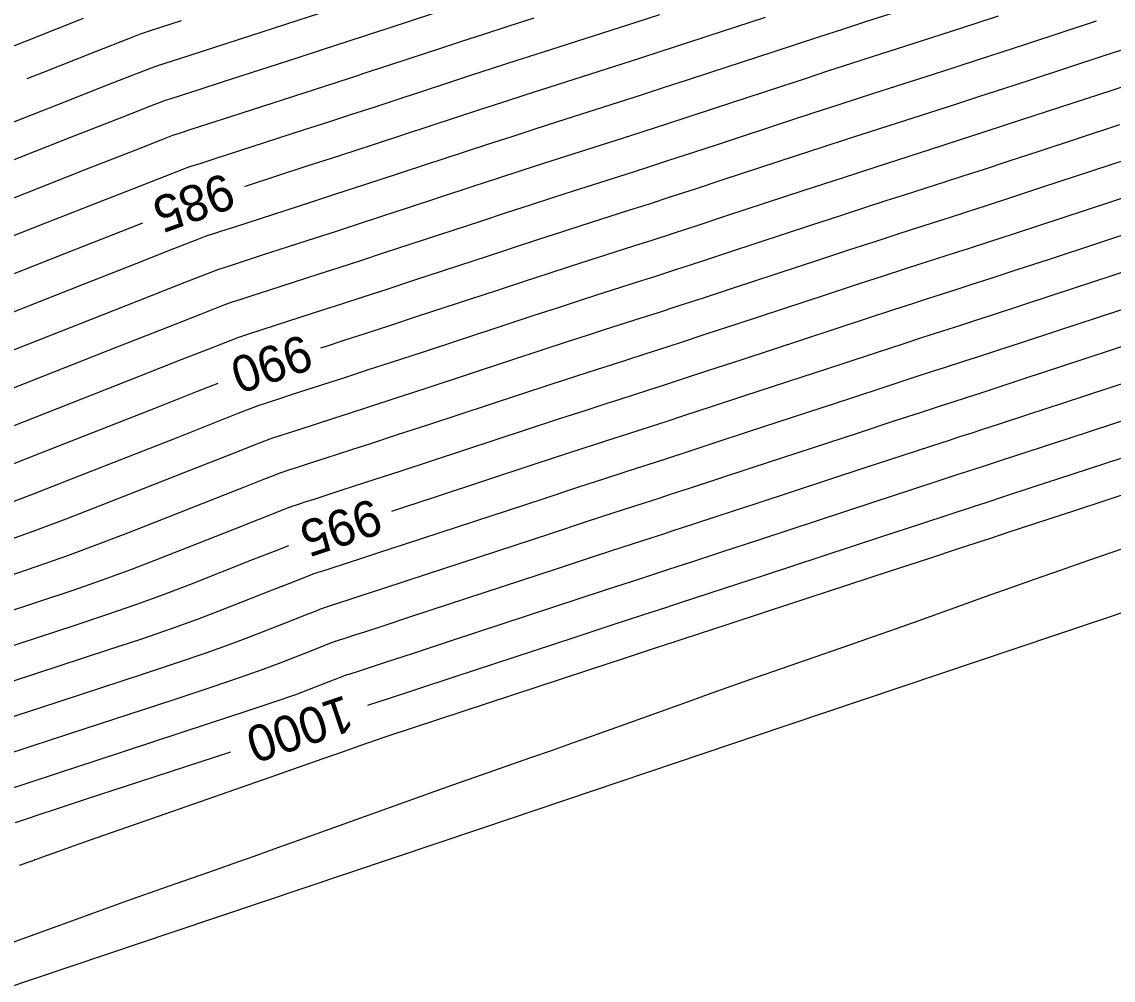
# Model space of a CAD drawing. Extents: x 2175772 to 2185556, y 721391 to 722853.
# Drawn here: x 2178849.6 to 2178934, y 721822.4 to 721896.5 of the extents above; entities that cross this region are included whole.
import ezdxf

# ---------------------------------------------------------------- set-up
doc = ezdxf.new("R2010")
doc.units = 0
for name, color, linetype in [('DT_X_Contour_Major', 7, 'Continuous'), ('DT_X_Contour_Minor', 7, 'Continuous'), ('DT_X_TIN_Hull', 7, 'Continuous')]:
    doc.layers.add(name, color=color, linetype=linetype)

msp = doc.modelspace()

# ---------------------------------------------------------------- linework, layer by layer
at = {"layer": 'DT_X_Contour_Major'}
for points in [[(2178850.015, 721892.08), (2178851.287, 721892.58), (2178855.384, 721894.192), (2178857.887, 721895.174), (2178858.796, 721895.527), (2178859.095, 721895.63), (2178859.488, 721895.759), (2178860.443, 721896.069), (2178861.959, 721896.56)], [(2178907.086, 721896.807), (2178902.576, 721895.326), (2178900.862, 721894.765), (2178899.102, 721894.193), (2178897.295, 721893.609), (2178895.442, 721893.013), (2178890.44, 721891.409), (2178888.585, 721890.813), (2178886.774, 721890.227), (2178885.006, 721889.652), (2178883.281, 721889.088), (2178877.024, 721887.035), (2178875.286, 721886.467), (2178873.524, 721885.895), (2178871.739, 721885.317), (2178866.948, 721883.769), (2178866.835, 721883.733)], [(2178935.904, 721891.824), (2178933.887, 721891.162), (2178927.874, 721889.189), (2178925.737, 721888.489), (2178923.836, 721887.869), (2178922.171, 721887.328), (2178920.742, 721886.868), (2178917.247, 721885.747), (2178915.816, 721885.286), (2178914.145, 721884.744), (2178912.235, 721884.121), (2178910.085, 721883.416), (2178904.033, 721881.43), (2178901.885, 721880.726), (2178899.98, 721880.104), (2178898.319, 721879.565), (2178896.901, 721879.108), (2178893.445, 721878), (2178892.026, 721877.543), (2178890.359, 721877.002), (2178888.445, 721876.377), (2178886.284, 721875.669), (2178880.191, 721873.669), (2178878.038, 721872.962), (2178876.147, 721872.344), (2178874.518, 721871.813), (2178873.152, 721871.37), (2178872.713, 721871.229)], [(2178858.933, 721880.894), (2178857.236, 721880.226), (2178852.9, 721878.519), (2178839.721, 721873.33)], [(2178936.883, 721877.801), (2178929.334, 721875.323), (2178926.765, 721874.48), (2178924.721, 721873.811), (2178923.201, 721873.316), (2178922.205, 721872.994), (2178920.249, 721872.367), (2178919.251, 721872.044), (2178917.724, 721871.547), (2178915.669, 721870.874), (2178913.085, 721870.026), (2178905.489, 721867.533), (2178902.907, 721866.686), (2178900.858, 721866.015), (2178899.343, 721865.521), (2178898.36, 721865.203), (2178896.451, 721864.591), (2178895.466, 721864.273), (2178893.944, 721863.777), (2178891.884, 721863.102), (2178889.287, 721862.25), (2178881.643, 721859.741), (2178879.051, 721858.89), (2178878.197, 721858.61)], [(2178864.773, 721868.496), (2178863.184, 721867.871), (2178860.205, 721866.699), (2178851.147, 721863.132), (2178847.944, 721861.886)], [(2178939.879, 721864.439), (2178930.794, 721861.457), (2178927.794, 721860.472), (2178925.606, 721859.754), (2178924.231, 721859.304), (2178923.668, 721859.12), (2178923.251, 721858.986), (2178921.303, 721858.349), (2178919.103, 721857.627), (2178916.084, 721856.636), (2178906.945, 721853.636), (2178903.929, 721852.646), (2178900.366, 721851.477), (2178899.819, 721851.299), (2178899.457, 721851.183), (2178898.907, 721851.003), (2178897.529, 721850.551), (2178895.323, 721849.827), (2178892.29, 721848.831), (2178883.096, 721845.813), (2178880.065, 721844.818), (2178877.869, 721844.097), (2178876.506, 721843.65), (2178876.344, 721843.597)], [(2178870.231, 721855.949), (2178869.133, 721855.517), (2178867.51, 721854.878), (2178862.573, 721852.934), (2178860.627, 721852.19), (2178858.49, 721851.413), (2178856.163, 721850.605), (2178853.645, 721849.766), (2178846.677, 721847.485)], [(2178865.742, 721839.993), (2178857.606, 721837.33), (2178854.6, 721836.346), (2178852.347, 721835.606), (2178850.846, 721835.11), (2178850.098, 721834.86), (2178849.105, 721834.517)]]:
    msp.add_lwpolyline(points, dxfattribs=at)
at = {"layer": 'DT_X_Contour_Minor'}
for points in [[(2178919.572, 721897.967), (2178914.845, 721896.452), (2178913.068, 721895.88), (2178911.282, 721895.302), (2178909.488, 721894.719), (2178907.686, 721894.129), (2178902.868, 721892.547), (2178901.067, 721891.957), (2178899.277, 721891.375), (2178897.5, 721890.8), (2178895.734, 721890.232), (2178891.041, 721888.727), (2178889.273, 721888.159), (2178887.491, 721887.582), (2178885.694, 721886.997), (2178883.882, 721886.404), (2178879.029, 721884.811), (2178877.227, 721884.22), (2178875.458, 721883.643), (2178873.723, 721883.079), (2178872.022, 721882.528), (2178866.046, 721880.597), (2178864.964, 721880.246), (2178864.282, 721880.025), (2178864.001, 721879.933), (2178863.788, 721879.859), (2178863.139, 721879.607), (2178861.351, 721878.906), (2178858.425, 721877.755), (2178854.361, 721876.155), (2178842.006, 721871.29)], [(2178835.15, 721877.409), (2178849.978, 721883.248), (2178854.856, 721885.168), (2178858.367, 721886.549), (2178860.513, 721887.39), (2178861.292, 721887.693), (2178861.548, 721887.782), (2178861.885, 721887.892), (2178862.703, 721888.158), (2178864.003, 721888.578), (2178865.783, 721889.154), (2178873.126, 721891.528), (2178874.941, 721892.117), (2178876.619, 721892.663), (2178878.158, 721893.168), (2178882.08, 721894.455), (2178883.63, 721894.962), (2178885.34, 721895.518), (2178887.209, 721896.121), (2178889.237, 721896.773)], [(2178898.926, 721897.011), (2178897.09, 721896.418), (2178895.151, 721895.794), (2178889.839, 721894.091), (2178887.897, 721893.467), (2178886.057, 721892.872), (2178884.318, 721892.307), (2178882.68, 721891.772), (2178878.449, 721890.382), (2178876.821, 721889.849), (2178875.113, 721889.292), (2178873.325, 721888.711), (2178871.456, 721888.106), (2178866.366, 721886.462), (2178864.684, 721885.918), (2178863.457, 721885.521), (2178862.684, 721885.27), (2178862.366, 721885.165), (2178862.124, 721885.082), (2178861.388, 721884.796), (2178859.362, 721884.001), (2178856.046, 721882.697), (2178851.439, 721880.884), (2178837.435, 721875.369)], [(2178844.135, 721892.704), (2178850.097, 721895.051), (2178854.389, 721896.739)], [(2178925.12, 721896.894), (2178923.305, 721896.303), (2178921.553, 721895.736), (2178919.865, 721895.192), (2178915.445, 721893.776), (2178913.755, 721893.232), (2178911.998, 721892.663), (2178910.175, 721892.069), (2178908.286, 721891.451), (2178903.159, 721889.768), (2178901.271, 721889.15), (2178899.453, 721888.557), (2178897.705, 721887.991), (2178896.026, 721887.451), (2178891.642, 721886.046), (2178889.961, 721885.505), (2178888.208, 721884.937), (2178886.382, 721884.342), (2178884.482, 721883.72), (2178879.32, 721882.025), (2178877.429, 721881.406), (2178875.63, 721880.818), (2178873.922, 721880.262), (2178872.304, 721879.738), (2178868.112, 721878.384), (2178866.728, 721877.936), (2178865.717, 721877.609), (2178865.081, 721877.403), (2178864.819, 721877.317), (2178864.62, 721877.248), (2178864.014, 721877.013), (2178862.346, 721876.358), (2178859.615, 721875.284), (2178855.822, 721873.791), (2178844.291, 721869.251)], [(2178847.057, 721887.976), (2178852.477, 721890.109), (2178856.378, 721891.644), (2178858.762, 721892.579), (2178859.628, 721892.916), (2178859.913, 721893.014), (2178860.287, 721893.137), (2178861.196, 721893.432), (2178862.64, 721893.899), (2178864.619, 721894.539), (2178872.729, 721897.16)], [(2178848.518, 721885.612), (2178853.666, 721887.639), (2178857.373, 721889.096), (2178859.638, 721889.985), (2178860.46, 721890.304), (2178860.731, 721890.398), (2178861.086, 721890.515), (2178861.95, 721890.795), (2178863.321, 721891.239), (2178865.201, 721891.847), (2178870.891, 721893.685), (2178872.928, 721894.344), (2178874.769, 721894.941), (2178876.416, 721895.478), (2178877.868, 721895.953), (2178881.479, 721897.139)], [(2178932.688, 721896.507), (2178927.29, 721894.735), (2178925.326, 721894.092), (2178923.482, 721893.491), (2178921.759, 721892.933), (2178920.157, 721892.418), (2178916.046, 721891.099), (2178914.442, 721890.583), (2178912.714, 721890.023), (2178910.862, 721889.42), (2178908.885, 721888.773), (2178903.45, 721886.988), (2178901.476, 721886.342), (2178899.629, 721885.74), (2178897.909, 721885.183), (2178896.318, 721884.67), (2178892.243, 721883.364), (2178890.65, 721882.851), (2178888.925, 721882.292), (2178887.069, 721881.687), (2178885.083, 721881.037), (2178879.61, 721879.24), (2178877.632, 721878.591), (2178875.802, 721877.993), (2178874.12, 721877.446), (2178872.587, 721876.949), (2178868.695, 721875.692), (2178867.409, 721875.276), (2178866.471, 721874.972), (2178865.88, 721874.78), (2178865.637, 721874.701), (2178865.452, 721874.637), (2178864.889, 721874.418), (2178863.34, 721873.81), (2178860.805, 721872.813), (2178857.283, 721871.427), (2178846.576, 721867.211)], [(2178935.208, 721894.465), (2178933.287, 721893.835), (2178927.582, 721891.962), (2178925.531, 721891.29), (2178923.659, 721890.68), (2178921.965, 721890.131), (2178920.45, 721889.643), (2178916.646, 721888.423), (2178915.129, 721887.935), (2178913.43, 721887.384), (2178911.548, 721886.77), (2178909.485, 721886.095), (2178903.741, 721884.209), (2178901.68, 721883.534), (2178899.804, 721882.922), (2178898.114, 721882.374), (2178896.609, 721881.889), (2178892.844, 721880.682), (2178891.338, 721880.197), (2178889.642, 721879.647), (2178887.757, 721879.032), (2178885.683, 721878.353), (2178879.901, 721876.454), (2178877.835, 721875.777), (2178875.974, 721875.169), (2178874.319, 721874.63), (2178872.869, 721874.16), (2178869.277, 721872.999), (2178868.09, 721872.615), (2178867.224, 721872.335), (2178866.679, 721872.158), (2178866.455, 721872.084), (2178866.284, 721872.025), (2178865.765, 721871.824), (2178864.335, 721871.263), (2178861.995, 721870.342), (2178858.744, 721869.063), (2178848.862, 721865.172)], [(2178934.486, 721888.49), (2178928.166, 721886.416), (2178925.943, 721885.687), (2178924.013, 721885.057), (2178922.377, 721884.526), (2178921.035, 721884.093), (2178917.847, 721883.071), (2178916.503, 721882.638), (2178914.861, 721882.105), (2178912.922, 721881.472), (2178910.685, 721880.738), (2178904.324, 721878.65), (2178902.089, 721877.918), (2178900.156, 721877.286), (2178898.524, 721876.756), (2178897.193, 721876.327), (2178894.047, 721875.319), (2178892.714, 721874.889), (2178891.076, 721874.357), (2178889.133, 721873.722), (2178886.885, 721872.985), (2178880.482, 721870.883), (2178878.24, 721870.148), (2178876.319, 721869.519), (2178874.717, 721868.997), (2178873.435, 721868.581), (2178870.442, 721867.614), (2178869.453, 721867.294), (2178868.731, 721867.061), (2178868.277, 721866.913), (2178868.09, 721866.852), (2178867.948, 721866.803), (2178867.515, 721866.635), (2178866.324, 721866.167), (2178864.374, 721865.401), (2178861.666, 721864.334), (2178853.432, 721861.092), (2178850.481, 721859.947), (2178847.802, 721858.942)], [(2178935.085, 721885.818), (2178928.458, 721883.642), (2178926.148, 721882.885), (2178924.19, 721882.246), (2178922.583, 721881.723), (2178921.327, 721881.318), (2178918.447, 721880.395), (2178917.19, 721879.989), (2178915.577, 721879.465), (2178913.609, 721878.822), (2178911.285, 721878.06), (2178904.615, 721875.871), (2178902.294, 721875.11), (2178900.331, 721874.469), (2178898.728, 721873.947), (2178897.485, 721873.546), (2178894.648, 721872.637), (2178893.402, 721872.235), (2178891.793, 721871.712), (2178889.821, 721871.067), (2178887.485, 721870.302), (2178880.772, 721868.097), (2178878.443, 721867.333), (2178876.491, 721866.695), (2178874.916, 721866.181), (2178873.717, 721865.792), (2178871.024, 721864.922), (2178870.134, 721864.634), (2178869.485, 721864.424), (2178869.076, 721864.291), (2178868.908, 721864.236), (2178868.78, 721864.192), (2178868.39, 721864.04), (2178867.318, 721863.62), (2178865.564, 721862.93), (2178863.127, 721861.97), (2178855.718, 721859.053), (2178853.017, 721858.008), (2178850.474, 721857.06), (2178848.087, 721856.209)], [(2178935.684, 721883.145), (2178926.354, 721880.084), (2178924.367, 721879.434), (2178922.789, 721878.921), (2178921.62, 721878.544), (2178919.048, 721877.719), (2178917.877, 721877.341), (2178916.293, 721876.826), (2178914.295, 721876.173), (2178911.885, 721875.382), (2178904.906, 721873.091), (2178902.498, 721872.302), (2178900.507, 721871.651), (2178898.933, 721871.139), (2178897.777, 721870.765), (2178895.249, 721869.955), (2178894.09, 721869.581), (2178892.51, 721869.067), (2178890.509, 721868.412), (2178888.086, 721867.618), (2178881.063, 721865.312), (2178878.646, 721864.519), (2178876.663, 721863.87), (2178875.115, 721863.364), (2178874, 721863.002), (2178871.606, 721862.229), (2178870.815, 721861.973), (2178870.238, 721861.787), (2178869.875, 721861.669), (2178869.725, 721861.62), (2178869.612, 721861.58), (2178869.266, 721861.446), (2178868.313, 721861.072), (2178866.754, 721860.459), (2178864.588, 721859.606), (2178858.003, 721857.013), (2178855.554, 721856.068), (2178853.146, 721855.178), (2178850.779, 721854.341), (2178848.453, 721853.56)], [(2178936.284, 721880.473), (2178929.042, 721878.096), (2178926.56, 721877.282), (2178924.544, 721876.623), (2178922.995, 721876.118), (2178921.913, 721875.769), (2178919.648, 721875.043), (2178918.564, 721874.693), (2178917.008, 721874.186), (2178914.982, 721873.523), (2178912.485, 721872.704), (2178905.198, 721870.312), (2178902.702, 721869.494), (2178900.683, 721868.833), (2178899.138, 721868.33), (2178898.068, 721867.984), (2178895.85, 721867.273), (2178894.778, 721866.927), (2178893.227, 721866.422), (2178891.196, 721865.757), (2178888.686, 721864.934), (2178881.353, 721862.526), (2178878.849, 721861.705), (2178876.835, 721861.045), (2178875.313, 721860.548), (2178874.283, 721860.213), (2178872.188, 721859.537), (2178871.497, 721859.313), (2178870.992, 721859.15), (2178870.674, 721859.046), (2178870.543, 721859.003), (2178870.444, 721858.969), (2178870.141, 721858.851), (2178869.308, 721858.524), (2178867.943, 721857.988), (2178866.049, 721857.242), (2178860.288, 721854.974), (2178858.091, 721854.129), (2178855.818, 721853.295), (2178853.471, 721852.473), (2178851.049, 721851.663), (2178844.491, 721849.516)], [(2178937.482, 721875.128), (2178929.626, 721872.55), (2178926.971, 721871.679), (2178924.898, 721871), (2178923.407, 721870.514), (2178922.498, 721870.219), (2178920.849, 721869.691), (2178919.938, 721869.396), (2178918.44, 721868.907), (2178916.356, 721868.224), (2178913.685, 721867.348), (2178905.78, 721864.753), (2178903.111, 721863.878), (2178901.034, 721863.198), (2178899.547, 721862.712), (2178898.652, 721862.423), (2178897.052, 721861.91), (2178896.155, 721861.619), (2178894.661, 721861.132), (2178892.572, 721860.447), (2178889.887, 721859.566), (2178881.934, 721856.955), (2178879.254, 721856.076), (2178877.18, 721855.396), (2178875.711, 721854.915), (2178874.848, 721854.634), (2178873.353, 721854.152), (2178872.859, 721853.992), (2178872.499, 721853.875), (2178872.272, 721853.802), (2178872.179, 721853.771), (2178872.108, 721853.746), (2178871.892, 721853.662), (2178871.297, 721853.429), (2178870.323, 721853.046), (2178868.97, 721852.514), (2178864.859, 721850.895), (2178863.164, 721850.25), (2178861.162, 721849.531), (2178858.855, 721848.738), (2178856.241, 721847.869), (2178848.863, 721845.454)], [(2178938.081, 721872.456), (2178929.918, 721869.776), (2178927.177, 721868.877), (2178925.075, 721868.189), (2178923.613, 721867.711), (2178922.79, 721867.444), (2178921.45, 721867.015), (2178920.625, 721866.747), (2178919.156, 721866.267), (2178917.042, 721865.575), (2178914.285, 721864.67), (2178906.071, 721861.974), (2178903.316, 721861.07), (2178901.209, 721860.38), (2178899.752, 721859.904), (2178898.944, 721859.642), (2178897.653, 721859.228), (2178896.843, 721858.965), (2178895.378, 721858.486), (2178893.26, 721857.792), (2178890.488, 721856.883), (2178882.224, 721854.17), (2178879.457, 721853.261), (2178877.352, 721852.571), (2178875.91, 721852.099), (2178875.13, 721851.845), (2178873.935, 721851.459), (2178873.541, 721851.331), (2178873.252, 721851.238), (2178873.071, 721851.179), (2178872.996, 721851.155), (2178872.94, 721851.135), (2178872.767, 721851.068), (2178872.291, 721850.881), (2178871.513, 721850.575), (2178870.431, 721850.15), (2178867.144, 721848.855), (2178865.7, 721848.311), (2178863.834, 721847.649), (2178861.547, 721846.87), (2178858.837, 721845.972), (2178851.049, 721843.423), (2178848.273, 721842.511)], [(2178938.68, 721869.783), (2178930.21, 721867.003), (2178927.382, 721866.075), (2178925.252, 721865.377), (2178923.819, 721864.909), (2178923.083, 721864.67), (2178922.05, 721864.339), (2178921.312, 721864.099), (2178919.872, 721863.628), (2178917.729, 721862.926), (2178914.884, 721861.992), (2178906.363, 721859.195), (2178903.52, 721858.262), (2178901.385, 721857.562), (2178899.957, 721857.095), (2178899.235, 721856.861), (2178898.255, 721856.546), (2178897.531, 721856.311), (2178896.095, 721855.841), (2178893.948, 721855.137), (2178891.089, 721854.199), (2178882.515, 721851.384), (2178879.66, 721850.447), (2178877.524, 721849.746), (2178876.109, 721849.283), (2178875.413, 721849.056), (2178874.518, 721848.767), (2178874.222, 721848.671), (2178874.006, 721848.601), (2178873.87, 721848.557), (2178873.814, 721848.539), (2178873.772, 721848.524), (2178873.642, 721848.474), (2178873.286, 721848.334), (2178872.703, 721848.104), (2178871.892, 721847.785), (2178869.429, 721846.816), (2178868.237, 721846.372), (2178866.507, 721845.767), (2178864.239, 721845.002), (2178861.433, 721844.076), (2178853.234, 721841.392), (2178850.382, 721840.456), (2178847.974, 721839.659)], [(2178939.28, 721867.111), (2178930.502, 721864.23), (2178925.429, 721862.566), (2178924.025, 721862.106), (2178923.375, 721861.895), (2178922.651, 721861.663), (2178921.999, 721861.45), (2178920.587, 721860.988), (2178918.416, 721860.276), (2178915.484, 721859.314), (2178906.654, 721856.415), (2178903.725, 721855.454), (2178901.561, 721854.744), (2178899.527, 721854.08), (2178898.856, 721853.864), (2178898.219, 721853.657), (2178896.812, 721853.196), (2178894.636, 721852.482), (2178882.805, 721848.598), (2178879.862, 721847.632), (2178877.696, 721846.922), (2178876.307, 721846.466), (2178875.696, 721846.267), (2178874.903, 721846.01), (2178874.759, 721845.964), (2178874.669, 721845.935), (2178874.632, 721845.922), (2178874.604, 721845.913), (2178874.28, 721845.786), (2178873.892, 721845.633), (2178873.353, 721845.421), (2178871.715, 721844.776), (2178870.773, 721844.432), (2178869.179, 721843.885), (2178866.931, 721843.134), (2178864.029, 721842.179), (2178855.42, 721839.361), (2178852.491, 721838.401), (2178850.161, 721837.633), (2178848.428, 721837.056)], [(2178940.478, 721861.766), (2178931.086, 721858.683), (2178927.999, 721857.67), (2178925.783, 721856.943), (2178924.436, 721856.501), (2178923.96, 721856.345), (2178923.852, 721856.31), (2178923.373, 721856.154), (2178922.019, 721855.709), (2178919.789, 721854.977), (2178916.684, 721853.958), (2178907.236, 721850.857), (2178904.134, 721849.838), (2178901.912, 721849.109), (2178900.571, 721848.669), (2178900.111, 721848.518), (2178900.058, 721848.501), (2178899.625, 721848.359), (2178898.365, 721847.945), (2178896.279, 721847.26), (2178893.366, 721846.304), (2178877.843, 721841.207), (2178876.776, 721840.835), (2178876.573, 721840.764), (2178876.42, 721840.711), (2178876.318, 721840.676), (2178876.267, 721840.657), (2178876.199, 721840.633), (2178875.749, 721840.475), (2178874.449, 721840.02), (2178872.299, 721839.268), (2178869.299, 721838.218), (2178860.166, 721835.024), (2178857.12, 721833.958), (2178854.833, 721833.156), (2178853.304, 721832.618), (2178852.533, 721832.344), (2178851.488, 721831.967), (2178851.141, 721831.841), (2178850.882, 721831.747), (2178850.712, 721831.685), (2178850.631, 721831.655), (2178850.533, 721831.618), (2178850.232, 721831.511), (2178849.404, 721831.219)], [(2178938.265, 721856.936), (2178932.101, 721854.805), (2178929.891, 721854.038), (2178927.882, 721853.336), (2178926.075, 721852.699), (2178924.47, 721852.126), (2178920.458, 721850.685), (2178918.897, 721850.127), (2178917.225, 721849.535), (2178915.441, 721848.909), (2178913.545, 721848.249), (2178908.34, 721846.441), (2178906.403, 721845.766), (2178904.496, 721845.094), (2178902.618, 721844.428), (2178900.77, 721843.766), (2178895.881, 721842.006), (2178894.073, 721841.357), (2178892.316, 721840.732), (2178890.611, 721840.13), (2178888.957, 721839.55), (2178884.615, 721838.037), (2178882.924, 721837.444), (2178881.108, 721836.801), (2178879.165, 721836.108), (2178877.097, 721835.364), (2178871.415, 721833.315), (2178869.384, 721832.584), (2178867.552, 721831.928), (2178865.918, 721831.348), (2178864.483, 721830.843), (2178860.922, 721829.598), (2178859.453, 721829.08), (2178857.718, 721828.463), (2178855.717, 721827.745), (2178853.449, 721826.928), (2178847.047, 721824.614)]]:
    msp.add_lwpolyline(points, dxfattribs=at)
at = {"layer": 'DT_X_TIN_Hull'}
msp.add_lwpolyline([(2178623.731, 721746.955), (2178647.535, 721754.586), (2178648.95, 721755.04), (2178672.703, 721762.834), (2178695.543, 721770.328), (2178719.209, 721778.379), (2178742.875, 721786.431), (2178746.708, 721787.735), (2178770.443, 721795.584), (2178794.178, 721803.433), (2178795.878, 721803.995), (2178819.557, 721812.012), (2178837.71, 721818.159), (2178861.405, 721826.129), (2178885.1, 721834.1), (2178908.796, 721842.07), (2178932.491, 721850.041), (2178956.186, 721858.011), (2178979.881, 721865.982), (2179003.576, 721873.952)], dxfattribs=at)

# ---------------------------------------------------------------- texts
at = {"layer": 'DT_X_Contour_Major'}
for s, rotation, p in [('985', 199.76278, (2178865.389, 721884.829)), ('990', 198.98944, (2178871.43, 721872.351)), ('995', 198.47425, (2178876.824, 721859.658)), ('1000', 198.7736, (2178874.618, 721844.429))]:
    msp.add_text(s, height=2.8, rotation=rotation, dxfattribs=at).set_placement(p)

doc.saveas('drawing.dxf')
